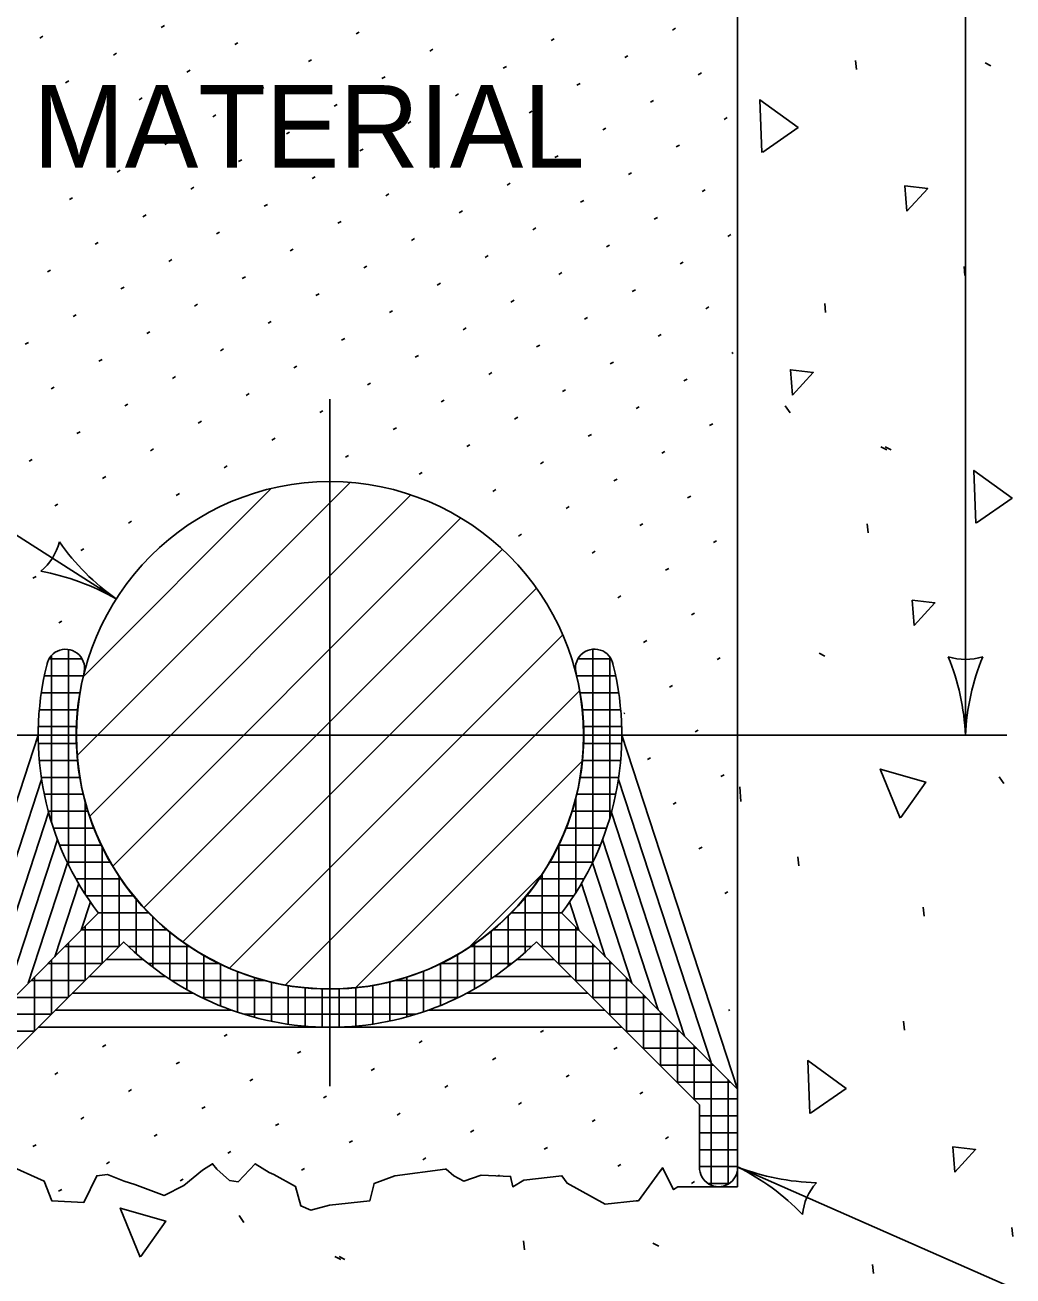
# Model space of a CAD drawing. Extents: x 49991.4 to 50021, y 49987.6 to 50011.4.
# Drawn here: x 50003.675 to 50004.633, y 49989.221 to 49990.433 of the extents above; entities that cross this region are included whole.
import ezdxf

# ---------------------------------------------------------------- set-up
doc = ezdxf.new("R2010")
doc.units = 0
for name, color, linetype in [('Level 1', 7, 'Continuous'), ('Level 15', 7, 'Continuous'), ('Level 2', 7, 'Continuous'), ('Level 3', 7, 'Continuous'), ('Level 4', 7, 'Continuous'), ('Level 6', 7, 'Continuous')]:
    doc.layers.add(name, color=color, linetype=linetype)

msp = doc.modelspace()

# ---------------------------------------------------------------- linework, layer by layer
at = {"layer": 'Level 1'}
for p, q in [((50003.7259, 49989.7252), (50003.9906, 49989.9898)), ((50003.7318, 49989.8018), (50003.914, 49989.984)), ((50003.738, 49989.6665), (50004.0493, 49989.9778)), ((50003.7603, 49989.6181), (50004.0976, 49989.9555)), ((50003.7907, 49989.5778), (50004.138, 49989.9251)), ((50003.8283, 49989.5447), (50004.1711, 49989.8875)), ((50003.8735, 49989.5192), (50004.1965, 49989.8421)), ((50003.7173, 49989.6196), (50003.7173, 49989.8279)), ((50004.2257, 49989.6218), (50004.2257, 49989.8283)), ((50003.6984, 49989.8188), (50003.7305, 49989.8188)), ((50003.7009, 49989.6606), (50003.7009, 49989.8221)), ((50004.2111, 49989.8188), (50004.2435, 49989.8188)), ((50004.2421, 49989.6641), (50004.2421, 49989.821)), ((50003.6939, 49989.8024), (50003.7317, 49989.8024)), ((50004.21, 49989.8024), (50004.2479, 49989.8024)), ((50003.9279, 49989.5029), (50004.2129, 49989.7879)), ((50003.691, 49989.786), (50003.7284, 49989.786)), ((50004.2135, 49989.786), (50004.2508, 49989.786)), ((50003.6891, 49989.7696), (50003.7262, 49989.7696)), ((50004.2153, 49989.7696), (50004.2527, 49989.7696)), ((50003.6881, 49989.7532), (50003.7251, 49989.7532)), ((50004.2168, 49989.7532), (50004.2537, 49989.7532)), ((50003.688, 49989.7449), (50003.5758, 49989.4019)), ((50004.2538, 49989.7449), (50004.366, 49989.4019)), ((50003.6881, 49989.7368), (50003.725, 49989.7368)), ((50004.2168, 49989.7368), (50004.2537, 49989.7368)), ((50003.6891, 49989.7204), (50003.7261, 49989.7204)), ((50003.9961, 49989.5003), (50004.2154, 49989.7197)), ((50004.2157, 49989.7204), (50004.2528, 49989.7204)), ((50003.691, 49989.704), (50003.7283, 49989.704)), ((50004.2135, 49989.704), (50004.2508, 49989.704)), ((50003.6913, 49989.7021), (50003.6015, 49989.4276)), ((50004.2506, 49989.7021), (50004.3404, 49989.4276)), ((50003.6939, 49989.6876), (50003.7317, 49989.6876)), ((50003.7337, 49989.5908), (50003.7337, 49989.6798)), ((50004.2093, 49989.5925), (50004.2093, 49989.684)), ((50004.2102, 49989.6876), (50004.248, 49989.6876)), ((50003.6981, 49989.6701), (50003.6271, 49989.4532)), ((50003.6978, 49989.6712), (50003.7362, 49989.6712)), ((50004.2056, 49989.6712), (50004.2441, 49989.6712)), ((50004.2438, 49989.6701), (50004.3147, 49989.4532)), ((50003.7027, 49989.6548), (50003.742, 49989.6548)), ((50004.1998, 49989.6548), (50004.2391, 49989.6548)), ((50003.7067, 49989.6437), (50003.6528, 49989.4789)), ((50004.2351, 49989.6438), (50004.2891, 49989.4789)), ((50003.7088, 49989.6384), (50003.7492, 49989.6384)), ((50003.7501, 49989.524), (50003.7501, 49989.6365)), ((50004.1927, 49989.6384), (50004.233, 49989.6384)), ((50004.1929, 49989.5229), (50004.1929, 49989.6388)), ((50003.7165, 49989.6211), (50003.6784, 49989.5045)), ((50003.7161, 49989.622), (50003.7578, 49989.622)), ((50004.184, 49989.622), (50004.2257, 49989.622)), ((50004.2253, 49989.6211), (50004.2635, 49989.5045)), ((50003.7665, 49989.5404), (50003.7665, 49989.608)), ((50004.1051, 49989.5387), (50004.1764, 49989.6099)), ((50004.1765, 49989.5393), (50004.1765, 49989.6097)), ((50003.7273, 49989.6011), (50003.7041, 49989.5302)), ((50003.7247, 49989.6056), (50003.7681, 49989.6056)), ((50004.1737, 49989.6056), (50004.2172, 49989.6056)), ((50004.2146, 49989.6011), (50004.2378, 49989.5302)), ((50003.7387, 49989.5833), (50003.7297, 49989.5558)), ((50003.7347, 49989.5892), (50003.7804, 49989.5892)), ((50003.7829, 49989.5335), (50003.7829, 49989.5863)), ((50004.1601, 49989.5345), (50004.1601, 49989.5876)), ((50004.1614, 49989.5892), (50004.2071, 49989.5892)), ((50004.2032, 49989.5833), (50004.2122, 49989.5558)), ((50003.5758, 49989.4019), (50003.7465, 49989.5726)), ((50003.7464, 49989.5728), (50003.7951, 49989.5728)), ((50004.1437, 49989.5208), (50004.1437, 49989.5697)), ((50004.1467, 49989.5728), (50004.1955, 49989.5728)), ((50004.1953, 49989.5726), (50004.366, 49989.4019)), ((50003.7337, 49989.5076), (50003.7337, 49989.5598)), ((50003.7993, 49989.52), (50003.7993, 49989.5686)), ((50004.2093, 49989.5065), (50004.2093, 49989.5587)), ((50003.7303, 49989.5564), (50003.8128, 49989.5564)), ((50003.8157, 49989.5084), (50003.8157, 49989.554)), ((50004.1273, 49989.5091), (50004.1273, 49989.5549)), ((50004.129, 49989.5564), (50004.2116, 49989.5564)), ((50003.7709, 49989.5448), (50003.6127, 49989.3867)), ((50003.7139, 49989.54), (50003.7661, 49989.54)), ((50003.7173, 49989.4912), (50003.7173, 49989.5434)), ((50003.7758, 49989.54), (50003.8347, 49989.54)), ((50003.8321, 49989.4984), (50003.8321, 49989.5418)), ((50004.1071, 49989.54), (50004.166, 49989.54)), ((50004.1109, 49989.499), (50004.1109, 49989.5425)), ((50004.3291, 49989.3866), (50004.171, 49989.5448)), ((50004.1758, 49989.54), (50004.228, 49989.54)), ((50004.2257, 49989.4901), (50004.2257, 49989.5423)), ((50003.6975, 49989.5236), (50003.7497, 49989.5236)), ((50003.7009, 49989.4748), (50003.7009, 49989.527)), ((50003.7536, 49989.5276), (50003.7898, 49989.5276)), ((50003.7946, 49989.5236), (50003.8634, 49989.5236)), ((50003.8485, 49989.4898), (50003.8485, 49989.5315)), ((50003.8649, 49989.4826), (50003.8649, 49989.5229)), ((50004.0781, 49989.483), (50004.0781, 49989.5234)), ((50004.0784, 49989.5236), (50004.1472, 49989.5236)), ((50004.0945, 49989.4903), (50004.0945, 49989.5321)), ((50004.1521, 49989.5276), (50004.1882, 49989.5276)), ((50004.1922, 49989.5236), (50004.2444, 49989.5236)), ((50004.2421, 49989.4737), (50004.2421, 49989.5259)), ((50003.6845, 49989.4584), (50003.6845, 49989.5106)), ((50003.7372, 49989.5112), (50003.8115, 49989.5112)), ((50003.8813, 49989.4765), (50003.8813, 49989.5158)), ((50003.8977, 49989.4716), (50003.8977, 49989.51)), ((50004.0453, 49989.4719), (50004.0453, 49989.5103)), ((50004.0617, 49989.4769), (50004.0617, 49989.5162)), ((50004.1304, 49989.5112), (50004.2046, 49989.5112)), ((50004.2585, 49989.4573), (50004.2585, 49989.5095)), ((50003.6811, 49989.5072), (50003.7333, 49989.5072)), ((50003.8175, 49989.5072), (50003.9074, 49989.5072)), ((50003.9141, 49989.4677), (50003.9141, 49989.5055)), ((50003.9305, 49989.4649), (50003.9305, 49989.5022)), ((50003.9469, 49989.463), (50003.9469, 49989.5)), ((50003.9633, 49989.462), (50003.9633, 49989.499)), ((50003.9797, 49989.4621), (50003.9797, 49989.499)), ((50003.9961, 49989.4631), (50003.9961, 49989.5001)), ((50004.0125, 49989.465), (50004.0125, 49989.5024)), ((50004.0289, 49989.4679), (50004.0289, 49989.5058)), ((50004.0344, 49989.5072), (50004.1244, 49989.5072)), ((50004.2086, 49989.5072), (50004.2608, 49989.5072)), ((50003.6647, 49989.4908), (50003.7169, 49989.4908)), ((50003.7208, 49989.4948), (50003.8387, 49989.4948)), ((50003.8465, 49989.4908), (50004.0953, 49989.4908)), ((50004.1032, 49989.4948), (50004.221, 49989.4948)), ((50004.225, 49989.4908), (50004.2772, 49989.4908)), ((50004.2749, 49989.4409), (50004.2749, 49989.4931)), ((50003.6483, 49989.4744), (50003.7005, 49989.4744)), ((50003.7044, 49989.4784), (50003.876, 49989.4784)), ((50003.888, 49989.4744), (50004.0538, 49989.4744)), ((50004.0659, 49989.4784), (50004.2374, 49989.4784)), ((50004.2414, 49989.4744), (50004.2936, 49989.4744)), ((50004.2913, 49989.4245), (50004.2913, 49989.4767)), ((50003.688, 49989.462), (50003.9719, 49989.462)), ((50003.973, 49989.462), (50004.2538, 49989.462)), ((50004.3077, 49989.4081), (50004.3077, 49989.4603)), ((50003.6319, 49989.458), (50003.684, 49989.458)), ((50004.2578, 49989.458), (50004.31, 49989.458)), ((50004.2742, 49989.4416), (50004.3264, 49989.4416)), ((50004.3241, 49989.3917), (50004.3241, 49989.4439)), ((50004.2906, 49989.4252), (50004.3428, 49989.4252)), ((50004.3405, 49989.3088), (50004.3405, 49989.4275)), ((50004.307, 49989.4088), (50004.3592, 49989.4088)), ((50004.3569, 49989.3099), (50004.3569, 49989.4111)), ((50004.366, 49989.4019), (50004.366, 49989.3265)), ((50004.3234, 49989.3924), (50004.366, 49989.3924)), ((50004.3291, 49989.3265), (50004.3291, 49989.3866)), ((50004.3291, 49989.376), (50004.366, 49989.376)), ((50004.3291, 49989.3596), (50004.366, 49989.3596)), ((50004.3291, 49989.3432), (50004.366, 49989.3432)), ((50004.3291, 49989.3268), (50004.366, 49989.3268)), ((50004.3375, 49989.3104), (50004.3576, 49989.3104))]:
    msp.add_line(p, q, dxfattribs=at)
msp.add_circle((50003.9709, 49989.7448), 0.2458, dxfattribs=at)
for centre, radius, start, end in [((50003.7145, 49989.8097), 0.0185, 342.3175, 169.8491), ((50004.2273, 49989.8099), 0.0184, 9.4354, 198.3869), ((50003.9709, 49989.7448), 0.2829, 166.075, 217.5046), ((50003.9709, 49989.7448), 0.2829, 322.4973, 13.925), ((50003.9709, 49989.7448), 0.246, 166.0753, 13.925), ((50003.9709, 49989.7448), 0.2829, 224.9996, 315.0002), ((50004.3476, 49989.3258), 0.0185, 177.9077, 2.0923)]:
    msp.add_arc(centre, radius, start, end, dxfattribs=at)
at = {"layer": 'Level 15'}
msp.add_line((50004.587, 49990.8781), (50004.587, 49989.7448), dxfattribs=at)
at = {"layer": 'Level 3'}
for p, q in [((50003.8072, 49990.4307), (50003.8103, 49990.4325)), ((50004.3029, 49990.4282), (50004.306, 49990.43)), ((50003.6896, 49990.4205), (50003.6926, 49990.4223)), ((50003.9962, 49990.4244), (50003.9993, 49990.4261)), ((50004.1853, 49990.418), (50004.1883, 49990.4198)), ((50003.7609, 49990.404), (50003.7639, 49990.4057)), ((50003.8786, 49990.4142), (50003.8816, 49990.4159)), ((50004.0676, 49990.4078), (50004.0706, 49990.4096)), ((50003.9499, 49990.3976), (50003.9529, 49990.3994)), ((50004.2566, 49990.4015), (50004.2596, 49990.4032)), ((50003.8322, 49990.3874), (50003.8353, 49990.3892)), ((50004.0212, 49990.3811), (50004.0243, 49990.3828)), ((50004.1389, 49990.3913), (50004.142, 49990.393)), ((50004.3279, 49990.3849), (50004.331, 49990.3867)), ((50003.7146, 49990.3772), (50003.7176, 49990.379)), ((50003.9036, 49990.3709), (50003.9066, 49990.3726)), ((50004.2103, 49990.3747), (50004.2133, 49990.3765)), ((50003.7859, 49990.3607), (50003.7889, 49990.3624)), ((50004.0926, 49990.3645), (50004.0956, 49990.3663)), ((50004.2816, 49990.3582), (50004.2846, 49990.3599)), ((50003.8572, 49990.3441), (50003.8603, 49990.3459)), ((50003.9749, 49990.3543), (50003.9779, 49990.3561)), ((50004.1639, 49990.348), (50004.167, 49990.3497)), ((50003.7396, 49990.3339), (50003.7426, 49990.3357)), ((50004.0462, 49990.3378), (50004.0493, 49990.3395)), ((50004.2353, 49990.3314), (50004.2383, 49990.3332)), ((50004.3529, 49990.3416), (50004.356, 49990.3434)), ((50003.9286, 49990.3276), (50003.9316, 49990.3293)), ((50004.1176, 49990.3212), (50004.1206, 49990.323)), ((50003.6932, 49990.3072), (50003.6962, 49990.3089)), ((50003.8109, 49990.3174), (50003.8139, 49990.3191)), ((50003.9999, 49990.311), (50004.0029, 49990.3128)), ((50004.3066, 49990.3149), (50004.3096, 49990.3166)), ((50003.8822, 49990.3008), (50003.8853, 49990.3026)), ((50004.1889, 49990.3047), (50004.192, 49990.3064)), ((50003.7646, 49990.2906), (50003.7676, 49990.2924)), ((50003.9536, 49990.2843), (50003.9566, 49990.286)), ((50004.0712, 49990.2945), (50004.0743, 49990.2962)), ((50004.2603, 49990.2881), (50004.2633, 49990.2899)), ((50003.8359, 49990.2741), (50003.8389, 49990.2758)), ((50004.1426, 49990.2779), (50004.1456, 49990.2797)), ((50004.3316, 49990.2716), (50004.3346, 49990.2733)), ((50003.7182, 49990.2639), (50003.7212, 49990.2656)), ((50004.0249, 49990.2677), (50004.0279, 49990.2695)), ((50004.2139, 49990.2614), (50004.217, 49990.2631)), ((50003.7896, 49990.2473), (50003.7926, 49990.2491)), ((50003.9072, 49990.2575), (50003.9103, 49990.2593)), ((50004.0962, 49990.2512), (50004.0993, 49990.2529)), ((50003.9786, 49990.241), (50003.9816, 49990.2427)), ((50004.1676, 49990.2346), (50004.1706, 49990.2364)), ((50004.2853, 49990.2448), (50004.2883, 49990.2466)), ((50003.8609, 49990.2308), (50003.8639, 49990.2325)), ((50004.0499, 49990.2244), (50004.0529, 49990.2262)), ((50004.3566, 49990.2283), (50004.3596, 49990.23)), ((50003.7432, 49990.2206), (50003.7462, 49990.2223)), ((50003.9322, 49990.2142), (50003.9353, 49990.216)), ((50004.2389, 49990.2181), (50004.242, 49990.2198)), ((50003.8146, 49990.204), (50003.8176, 49990.2058)), ((50004.1212, 49990.2079), (50004.1243, 49990.2096)), ((50004.3103, 49990.2015), (50004.3133, 49990.2033)), ((50003.6969, 49990.1938), (50003.6999, 49990.1955)), ((50003.8859, 49990.1875), (50003.8889, 49990.1892)), ((50004.0036, 49990.1977), (50004.0066, 49990.1994)), ((50004.1926, 49990.1913), (50004.1956, 49990.1931)), ((50003.7682, 49990.1773), (50003.7712, 49990.179)), ((50004.0749, 49990.1811), (50004.0779, 49990.1829)), ((50004.2639, 49990.1748), (50004.267, 49990.1765)), ((50003.9572, 49990.1709), (50003.9603, 49990.1727)), ((50004.1462, 49990.1646), (50004.1493, 49990.1663)), ((50003.7219, 49990.1505), (50003.7249, 49990.1522)), ((50003.8396, 49990.1607), (50003.8426, 49990.1625)), ((50004.0286, 49990.1544), (50004.0316, 49990.1561)), ((50004.3353, 49990.1582), (50004.3383, 49990.16)), ((50003.9109, 49990.1442), (50003.9139, 49990.1459)), ((50004.0999, 49990.1378), (50004.1029, 49990.1396)), ((50004.2176, 49990.148), (50004.2206, 49990.1498)), ((50003.7932, 49990.134), (50003.7962, 49990.1357)), ((50003.9822, 49990.1276), (50003.9853, 49990.1294)), ((50004.2889, 49990.1315), (50004.292, 49990.1332)), ((50003.6755, 49990.1237), (50003.6786, 49990.1255)), ((50003.8646, 49990.1174), (50003.8676, 49990.1192)), ((50004.1712, 49990.1213), (50004.1743, 49990.123)), ((50004.3603, 49990.1149), (50004.3619, 49990.1159)), ((50003.7469, 49990.1072), (50003.7499, 49990.1089)), ((50004.0536, 49990.1111), (50004.0566, 49990.1128)), ((50004.2426, 49990.1047), (50004.2456, 49990.1065)), ((50003.8182, 49990.0906), (50003.8212, 49990.0924)), ((50003.9359, 49990.1009), (50003.9389, 49990.1026)), ((50004.1249, 49990.0945), (50004.1279, 49990.0963)), ((50003.7005, 49990.0804), (50003.7036, 49990.0822)), ((50004.0072, 49990.0843), (50004.0103, 49990.0861)), ((50004.1962, 49990.078), (50004.1993, 49990.0797)), ((50004.3139, 49990.0882), (50004.317, 49990.0899)), ((50003.8896, 49990.0741), (50003.8926, 49990.0759)), ((50003.9709, 49990.0706), (50003.9709, 49989.4048)), ((50004.0786, 49990.0678), (50004.0816, 49990.0695)), ((50003.7719, 49990.0639), (50003.7749, 49990.0656)), ((50003.9609, 49990.0576), (50003.9639, 49990.0593)), ((50004.2676, 49990.0614), (50004.2706, 49990.0632)), ((50003.8432, 49990.0473), (50003.8462, 49990.0491)), ((50004.0322, 49990.041), (50004.0353, 49990.0428)), ((50004.1499, 49990.0512), (50004.1529, 49990.053)), ((50004.3389, 49990.0449), (50004.342, 49990.0466)), ((50003.7255, 49990.0371), (50003.7286, 49990.0389)), ((50003.9146, 49990.0308), (50003.9176, 49990.0326)), ((50004.2212, 49990.0347), (50004.2243, 49990.0364)), ((50003.7969, 49990.0206), (50003.7999, 49990.0223)), ((50004.1036, 49990.0245), (50004.1066, 49990.0262)), ((50004.2926, 49990.0181), (50004.2956, 49990.0199)), ((50003.6792, 49990.0104), (50003.6822, 49990.0121)), ((50003.8682, 49990.004), (50003.8712, 49990.0058)), ((50003.9859, 49990.0143), (50003.9889, 49990.016)), ((50004.1749, 49990.0079), (50004.1779, 49990.0097)), ((50003.7505, 49989.9938), (50003.7536, 49989.9956)), ((50004.0572, 49989.9977), (50004.0603, 49989.9995)), ((50004.1286, 49989.9812), (50004.1316, 49989.9829)), ((50004.2462, 49989.9914), (50004.2493, 49989.9931)), ((50003.8219, 49989.9773), (50003.8249, 49989.979)), ((50004.3176, 49989.9748), (50004.3206, 49989.9766)), ((50003.7042, 49989.9671), (50003.7072, 49989.9688)), ((50004.1999, 49989.9646), (50004.2029, 49989.9664)), ((50003.7755, 49989.9505), (50003.7786, 49989.9523)), ((50004.2712, 49989.9481), (50004.2743, 49989.9498)), ((50004.1536, 49989.9379), (50004.1566, 49989.9396)), ((50004.3426, 49989.9315), (50004.3456, 49989.9333)), ((50003.7292, 49989.9238), (50003.7322, 49989.9255)), ((50004.2249, 49989.9213), (50004.2279, 49989.9231)), ((50003.6829, 49989.897), (50003.6859, 49989.8988)), ((50004.2962, 49989.9048), (50004.2993, 49989.9065)), ((50004.2499, 49989.878), (50004.2529, 49989.8798)), ((50004.3212, 49989.8615), (50004.3243, 49989.8632)), ((50003.7079, 49989.8537), (50003.7109, 49989.8555)), ((50004.2749, 49989.8347), (50004.2779, 49989.8365)), ((50004.3462, 49989.8182), (50004.3493, 49989.8199)), ((50004.2999, 49989.7914), (50004.3029, 49989.7932)), ((50004.2558, 49989.7659), (50004.2566, 49989.7664)), ((50003.628, 49989.7448), (50004.627, 49989.7448)), ((50004.3249, 49989.7481), (50004.3279, 49989.7499)), ((50004.2786, 49989.7213), (50004.2816, 49989.7231)), ((50004.3499, 49989.7048), (50004.3529, 49989.7066)), ((50004.3036, 49989.678), (50004.3066, 49989.6798)), ((50004.3286, 49989.6347), (50004.3316, 49989.6365)), ((50004.3536, 49989.5914), (50004.3566, 49989.5932)), ((50004.3572, 49989.4781), (50004.3584, 49989.4788)), ((50003.8682, 49989.4532), (50003.8712, 49989.455)), ((50004.0572, 49989.4469), (50004.0602, 49989.4486)), ((50004.1749, 49989.4571), (50004.1779, 49989.4588)), ((50003.7505, 49989.443), (50003.7535, 49989.4447)), ((50003.9395, 49989.4367), (50003.9426, 49989.4384)), ((50004.2462, 49989.4405), (50004.2492, 49989.4423)), ((50003.8218, 49989.4265), (50003.8249, 49989.4282)), ((50004.1285, 49989.4303), (50004.1316, 49989.4321)), ((50003.7042, 49989.4162), (50003.7072, 49989.418)), ((50004.0109, 49989.4201), (50004.0139, 49989.4219)), ((50004.1999, 49989.4138), (50004.2029, 49989.4155)), ((50003.7755, 49989.3997), (50003.7785, 49989.4014)), ((50003.8932, 49989.4099), (50003.8962, 49989.4117)), ((50004.0822, 49989.4036), (50004.0852, 49989.4053)), ((50003.9645, 49989.3934), (50003.9676, 49989.3951)), ((50004.1535, 49989.387), (50004.1566, 49989.3888)), ((50004.2712, 49989.3972), (50004.2742, 49989.399)), ((50003.8468, 49989.3832), (50003.8499, 49989.3849)), ((50004.0359, 49989.3768), (50004.0389, 49989.3786)), ((50003.7292, 49989.3729), (50003.7322, 49989.3747)), ((50003.9182, 49989.3666), (50003.9212, 49989.3684)), ((50004.2249, 49989.3705), (50004.2279, 49989.3722)), ((50003.8005, 49989.3564), (50003.8035, 49989.3581)), ((50003.9895, 49989.3501), (50003.9926, 49989.3518)), ((50004.1072, 49989.3603), (50004.1102, 49989.362)), ((50004.2962, 49989.3539), (50004.2992, 49989.3557)), ((50003.6828, 49989.3462), (50003.6859, 49989.3479)), ((50003.8718, 49989.3398), (50003.8749, 49989.3416)), ((50004.1785, 49989.3437), (50004.1816, 49989.3455)), ((50003.7542, 49989.3296), (50003.7572, 49989.3314)), ((50004.0609, 49989.3335), (50004.0639, 49989.3353)), ((50004.2499, 49989.3272), (50004.2529, 49989.3289)), ((50003.8255, 49989.3131), (50003.8285, 49989.3148)), ((50003.9432, 49989.3233), (50003.9462, 49989.3251)), ((50004.1338, 49989.3179), (50004.1352, 49989.3187)), ((50003.7078, 49989.3029), (50003.7109, 49989.3046)), ((50004.3212, 49989.3106), (50004.3242, 49989.3124))]:
    msp.add_line(p, q, dxfattribs=at)
for points in [[(50003.5216, 49990.0314), (50003.7637, 49989.877)], [(50005.8817, 49988.6593), (50004.366, 49989.3265)]]:
    msp.add_lwpolyline(points, dxfattribs=at)
for centre, radius, start, end in [((50003.6556, 49989.946), 0.0548, 309.6073, 345.3297), ((50003.8909, 49990.0594), 0.2223, 214.9245, 235.108), ((50003.6482, 49989.6746), 0.233, 60.2958, 79.5457), ((50004.587, 49989.8731), 0.0548, 252.1388, 287.8612), ((50004.3543, 49989.7334), 0.233, 2.8273, 22.0772), ((50004.8091, 49989.7357), 0.2223, 157.456, 177.6395), ((50004.2682, 49989.1268), 0.2223, 43.728, 63.9115), ((50004.4491, 49989.5441), 0.233, 249.0993, 268.3492), ((50004.4834, 49989.2749), 0.0548, 138.4108, 174.1332)]:
    msp.add_arc(centre, radius, start, end, dxfattribs=at)
at = {"layer": 'Level 4'}
for p, q in [((50004.4814, 49990.3901), (50004.4805, 49990.3988)), ((50004.606, 49990.3964), (50004.6117, 49990.3936)), ((50004.5865, 49990.1903), (50004.5856, 49990.199)), ((50004.4514, 49990.1544), (50004.4505, 49990.1631)), ((50004.4121, 49990.0639), (50004.4169, 49990.0574)), ((50004.505, 49990.0243), (50004.5107, 49990.0215)), ((50004.509, 49990.0243), (50004.5148, 49990.0215)), ((50004.4925, 49989.9411), (50004.4916, 49989.9498)), ((50004.445, 49989.8245), (50004.4507, 49989.8216)), ((50004.6195, 49989.7047), (50004.6243, 49989.6982)), ((50004.4255, 49989.6184), (50004.4246, 49989.6271)), ((50004.547, 49989.5696), (50004.5461, 49989.5783)), ((50004.5278, 49989.459), (50004.5269, 49989.4677)), ((50003.8828, 49989.2793), (50003.8875, 49989.2728)), ((50004.6329, 49989.2592), (50004.632, 49989.2679)), ((50004.1595, 49989.2463), (50004.1585, 49989.255)), ((50004.284, 49989.2526), (50004.2897, 49989.2497)), ((50003.9756, 49989.2397), (50003.9813, 49989.2369)), ((50003.9797, 49989.2397), (50003.9854, 49989.2369)), ((50004.4978, 49989.2232), (50004.4969, 49989.2319))]:
    msp.add_line(p, q, dxfattribs=at)
for points in [[(50004.3896, 49990.3094), (50004.3877, 49990.3606), (50004.4247, 49990.3338), (50004.3904, 49990.3099)], [(50004.5302, 49990.2527), (50004.5283, 49990.2773), (50004.5504, 49990.2746), (50004.5302, 49990.2527)], [(50004.4192, 49990.0745), (50004.4173, 49990.0991), (50004.4394, 49990.0964), (50004.4192, 49990.0745)], [(50004.597, 49989.9502), (50004.5951, 49990.0014), (50004.6321, 49989.9746), (50004.5978, 49989.9506)], [(50004.5373, 49989.8511), (50004.5354, 49989.8757), (50004.5574, 49989.873), (50004.5373, 49989.8511)], [(50004.5237, 49989.6645), (50004.5044, 49989.712), (50004.5484, 49989.6994), (50004.5243, 49989.6652)], [(50004.3692, 49989.6808), (50004.3682, 49989.6947)], [(50004.436, 49989.3783), (50004.4341, 49989.4295), (50004.4712, 49989.4026), (50004.4368, 49989.3787)], [(50004.5766, 49989.3215), (50004.5748, 49989.3461), (50004.5968, 49989.3434), (50004.5766, 49989.3215)], [(50003.7869, 49989.2391), (50003.7676, 49989.2866), (50003.8116, 49989.274), (50003.7875, 49989.2398)]]:
    msp.add_lwpolyline(points, dxfattribs=at)
at = {"layer": 'Level 6'}
for p, q in [((50004.366, 49990.8725), (50004.366, 49989.9969)), ((50004.366, 49989.9969), (50004.366, 49989.3073)), ((50004.2897, 49989.3209), (50004.2942, 49989.3255)), ((50004.308, 49989.3073), (50004.366, 49989.3073))]:
    msp.add_line(p, q, dxfattribs=at)
msp.add_lwpolyline([(50003.6578, 49989.329), (50003.6939, 49989.3127), (50003.7013, 49989.2936), (50003.7324, 49989.2922), (50003.7447, 49989.318), (50003.7553, 49989.3191), (50003.7712, 49989.3127), (50003.7818, 49989.3095), (50003.8102, 49989.299), (50003.8292, 49989.3086), (50003.8474, 49989.3233), (50003.857, 49989.3296), (50003.8612, 49989.3243), (50003.8735, 49989.3133), (50003.8819, 49989.3122), (50003.8983, 49989.3296), (50003.912, 49989.3212), (50003.9164, 49989.3192), (50003.9375, 49989.3076), (50003.9426, 49989.2887), (50003.9522, 49989.2845), (50003.9703, 49989.2894), (50004.0095, 49989.2936), (50004.0137, 49989.3106), (50004.0137, 49989.3106), (50004.0338, 49989.318), (50004.0825, 49989.3243), (50004.0835, 49989.3243), (50004.091, 49989.318), (50004.1005, 49989.3127), (50004.1174, 49989.3185), (50004.146, 49989.3174), (50004.1481, 49989.3074), (50004.1587, 49989.3138), (50004.1958, 49989.318), (50004.2007, 49989.3107), (50004.2378, 49989.2906), (50004.2678, 49989.2936), (50004.2699, 49989.2936), (50004.2931, 49989.3257), (50004.304, 49989.3045), (50004.308, 49989.3073)], dxfattribs=at)

# ---------------------------------------------------------------- texts
at = {"layer": 'Level 2'}
msp.add_text('MATERIAL', height=0.08, dxfattribs=at).set_placement((50003.6828, 49990.2948))

doc.saveas('drawing.dxf')
